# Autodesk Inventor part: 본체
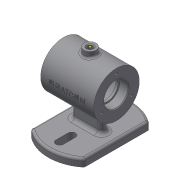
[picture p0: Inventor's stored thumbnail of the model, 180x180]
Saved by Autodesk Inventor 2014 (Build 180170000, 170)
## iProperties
Created: 2017-12
Part Number: 본체
Material: Generic
Document SubType Name: Modeling
Designer: user
Density: 1 g/cm^3
Appearance: Default
Author: user
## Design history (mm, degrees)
sketch "스케치1"
  geometry: L1 (0, 55)-(0, -55); L2 (35, 42.426)-(35, -42.426); L3 (-35, 42.426)-(-35, -42.426); L4 (0, 40)-(0, 24); L5 (-5, 40)-(-5, 24); L6 (5, 24)-(5, 40); L7 (0, 0)-(-16.976, 0); L8 (-5, -40)-(-5, -24); L9 (5, -24)-(5, -40); A1 r 55 centre (0, 0) between (35, 42.426) and (-35, 42.426); A2 r 55 centre (0, 0) between (-35, -42.426) and (35, -42.426); A3 r 5 centre (0, 40) between (5, 40) and (-5, 40); A4 r 5 centre (0, 24) between (-5, 24) and (5, 24); A5 r 5 centre (0, -40) between (-5, -40) and (5, -40); A6 r 5 centre (0, -24) between (5, -24) and (-5, -24); 2 further points
  constraints: 20 end point, 14 point on circle, 6 centre point, 6 symmetric about line, 4 tangent, 3 parallel, 2 coincident, 2 midpoint, 2 point on line, 1 perpendicular, 1 vertical, 2 other
  dimensions: "d2" = 35 distance between parallel lines of L2 L1; "d3" = 35 distance between parallel lines of L3 L1; "d4" = 16 distance of L6.start L6.end; "d5" = 24 distance of point (0, 0) L4.end; "d6" = 5 radius of A3
extrude "돌출1" new body sketch "스케치1" distance "d7" = 10; taper "d8" = 0 deg
sketch "스케치2"
  geometry: L1 (-35, 92)-(35, 92); L2 (35, 92)-(35, 62); L3 (35, 62)-(-35, 62); L4 (-35, 62)-(-35, 92); L5 (-35, 0)-(35, 0) reference; 3 further points
  constraints: 8 end point, 2 midpoint, 2 parallel, 2 vertical alignment, 1 horizontal, 1 perpendicular
  dimensions: "d9" = 62 distance between parallel lines of L3 L5; "d10" = 30 distance of L3.end L1.start; "d21" = 70 distance of L1.start L1.end
revolve "회전1" sketch "스케치2" stored, may be unused: angle "d11" = 90 deg
sketch "스케치3"
  geometry: L1 (-15, 0)-(15, 0); L2 (-15, -5)-(15, -5); L3 (15, 5)-(-15, 5); A1 r 5 centre (-15, 0) between (-15, 5) and (-15, -5); A2 r 5 centre (15, 0) between (15, -5) and (15, 5); 1 further point
  constraints: 8 end point, 4 point on circle, 4 tangent, 2 centre point, 1 horizontal, 1 midpoint, 1 parallel
  dimensions: "d12" = 30 distance of L3.start L3.end; "d13" = 5 radius of A1
extrude "돌출2" join sketch "스케치3" stored distance "d14" = 10; taper "d15" = 0 deg
node "작업 평면1"
sketch "스케치4"
  geometry: 1 further point
sketch "스케치5"
  geometry: L1 (35, -30)-(35, 30) reference; C1 r 8 at (0, 0); 1 further point
  constraints: 1 centre point
  dimensions: "d18" = 35 distance from line of C1.centre L1; "d59" = 16 diameter of C1
extrude "돌출3" join sketch "스케치5" stored distance "d19" = 10; taper "d20" = 0 deg
fillet "모깎기1" dims "d22" = 3
sketch "스케치6"
  geometry: L1 (-35, 32)-(-35, 92) reference; L2 (35, 32)-(35, 92) reference; L3 (-35, 62)-(-23, 62); L4 (-23, 62)-(-23, 78); L5 (-23, 78)-(-35, 78); L6 (-35, 78)-(-35, 62); L7 (-23, 62)-(-20, 62); L8 (-20, 62)-(-20, 76); L9 (-20, 76)-(-23, 76); L10 (-23, 76)-(-23, 62); L11 (-20, 62)-(20, 62); L12 (20, 62)-(20, 87); L13 (20, 87)-(-20, 87); L14 (-20, 87)-(-20, 62); L15 (20, 62)-(23, 62); L16 (23, 62)-(23, 76); L17 (23, 76)-(20, 76); L18 (20, 76)-(20, 62); L19 (23, 62)-(35, 62); L20 (35, 62)-(35, 78); L21 (35, 78)-(23, 78); L22 (23, 78)-(23, 62); 1 further point
  constraints: 40 end point, 10 parallel, 5 horizontal, 5 perpendicular, 3 collinear, 1 midpoint
  dimensions: "d23" = 12 distance of L4.end L5.end; "d24" = 3 distance of L8.end L9.end; "d25" = 3 distance of L16.end L17.end; "d26" = 12 distance of L20.end L21.end; "d27" = 14 distance between parallel lines of L7 L9; "d28" = 16 distance between parallel lines of L3 L5; "d29" = 25 distance between parallel lines of L11 L13
revolve "회전2" sketch "스케치6" stored, may be unused: angle "d30" = 90 deg
fillet "모깎기2" dims "d31" = 3
fillet "모깎기3" dims "d32" = 0.3
chamfer "모따기1" distance "d33" = 1; stored, may be unused: second distance "d34" = 2, angle "d35" = 45 deg
sketch "스케치7"
  geometry: C1 r 4 at (0, 0); 1 further point
  constraints: 1 centre point, 1 coincident
  dimensions: "d36" = 8 diameter of C1
extrude "돌출4" cut sketch "스케치7" stored distance "d37" = 10; taper "d38" = 0 deg
chamfer "모따기2" distance "d39" = 1; stored, may be unused: second distance "d40" = 2, angle "d41" = 45 deg
sketch "스케치8" dims "d42" = 46
  geometry: C1 r 30 at (0, 0) reference; 5 further points
  constraints: 2 vertical alignment, 7 other
  dimensions: "d45" = 360 deg dimension on point (0, 0) point (0, 23) (derived)
hole "구멍1" sketch "스케치8" at (0, 23), (-19.919, -11.5), (19.919, -11.5) diameter "d47" = 3.242; stored, may be unused: countersink angle "d51" = 90 deg, drill point angle "d53" = 118 deg; dims "d48" = 8, "d49" = 4, "d50" = 2, "d52" = 10
fillet "모깎기4" dims "d60" = 5
node "작업 평면3"
sketch "스케치10"
  geometry: L1 (-20, 17)-(-20, 77) reference; L2 (23, 84)-(7, 84) reference; L3 (-20, 77)-(50, 77) reference; 2 further points
  constraints: 1 other
  dimensions: "d62" = 35 distance from line of point (15, 47) L1; "d66" = 30 distance from line of point (15, 47) L3
feature "엠보싱2" sketch "스케치10" dims "d9" = 62, "d10" = 30, "d21" = 70, "d64" = 0.5, "d65" = 0
node "솔리드1"
mirror "대칭1"
other parameters: "d16" = -99
